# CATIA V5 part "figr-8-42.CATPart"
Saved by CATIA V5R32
Part number: Part1
Bounding box of the stored display mesh (mm): x -75 to 75, y -75 to 75, z 0 to 20
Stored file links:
  D:\PROJECTS\Project 2022\CATIA V5 6R 2022\Resources\Part Files\c08_catia_v5_6r2022_prt\figr-8-42.CATPart
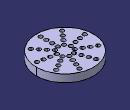
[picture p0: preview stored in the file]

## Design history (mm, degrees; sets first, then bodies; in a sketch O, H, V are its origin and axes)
Body1 (main body)
  Sketch1 on xy-plane, origin (0, 0, 0), H (1, 0, 0), V (0, 1, 0)
    circle A1 centre (0, 0) radius 75
    point P1 (75, 0)
    radius A1 = 75
    coincidence: A1 P1, P1 H
  Pad1: profile Sketch1, direction (0, 0, 1), length 20
  Sketch2 on face of Pad1, origin (0, 0, 20), H (1, 0, 0), V (0, 1, 0)
    circle A1 centre (0, -18.7232) radius 5.1678
    point P1 (0, -18.7232)
    coincidence: P1 V
  Pocket1: profile Sketch2, direction (0, 0, -1), through (limit type 3)
  CircPattern1: of Pocket1, instances 9, angular step 40 {= 360.0*1 deg/CircPattern1.AngularNumber}, circles 4, radial step 15, axis from face of Pad1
